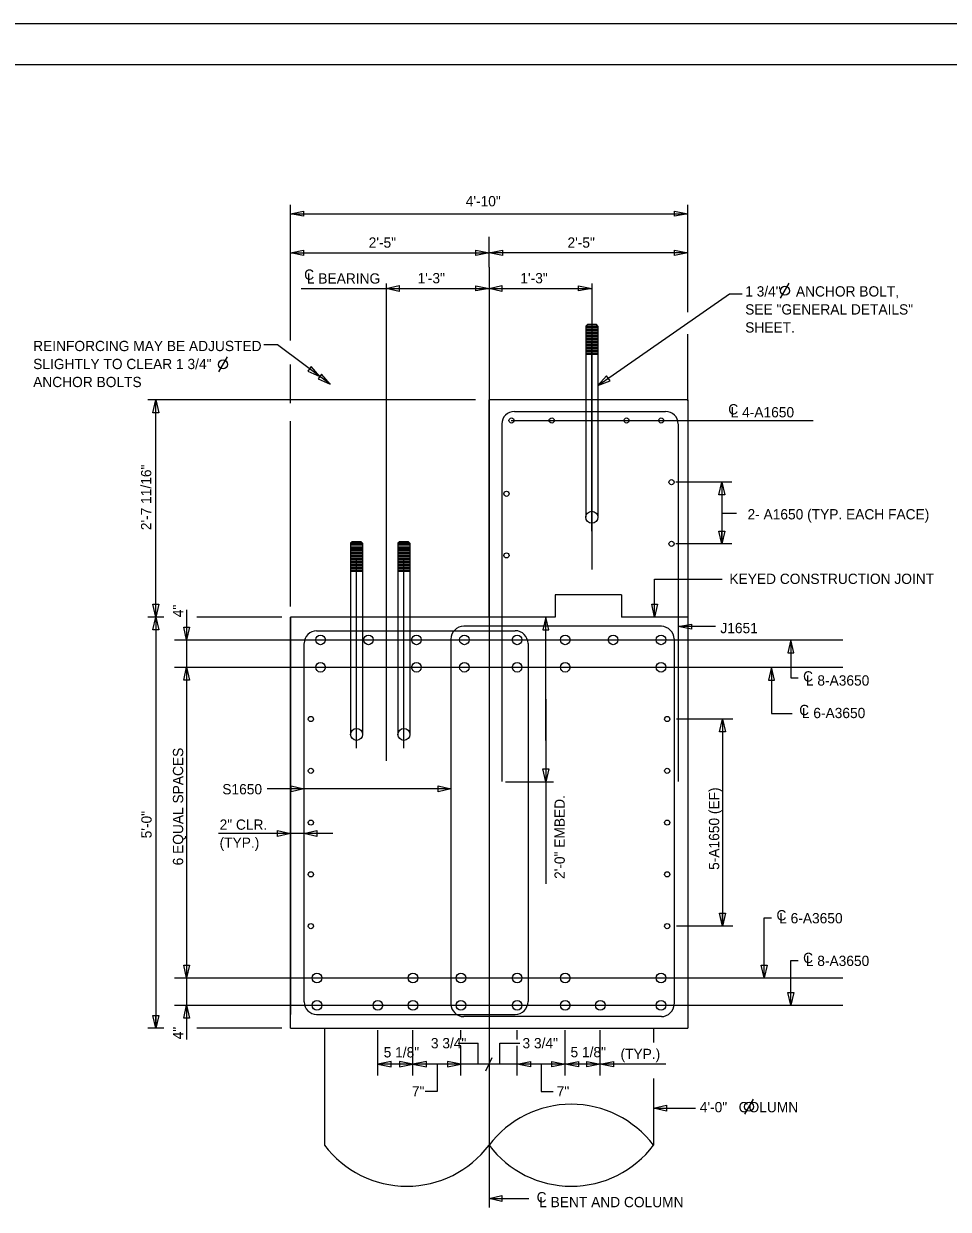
# Model space of a CAD drawing. Extents: x 1970675.2 to 1970711.3, y 796145.2 to 796167.2.
# Drawn here: x 1970689.32 to 1970700.57, y 796152.83 to 796167.25 of the extents above; entities that cross this region are included whole.
import ezdxf

# ---------------------------------------------------------------- set-up
doc = ezdxf.new("R2010")
doc.units = 0
for name, color, linetype in [('BR_AUTO DIMENSION', 7, 'Continuous'), ('BR_BORDER LINES', 7, 'Continuous'), ('BR_CENTER LINES', 7, 'Continuous'), ('BR_CONCRETE', 7, 'Continuous'), ('BR_REBAR', 7, 'Continuous'), ('BR_STRUCTURAL STEEL', 7, 'Continuous'), ('BR_TEXT', 7, 'Continuous'), ('Level 31', 7, 'Continuous')]:
    doc.layers.add(name, color=color, linetype=linetype)

msp = doc.modelspace()

# ---------------------------------------------------------------- linework, layer by layer
at = {"layer": 'BR_AUTO DIMENSION'}
for p, q in [((1970692.565, 796163.394), (1970692.565, 796165.043)), ((1970697.398, 796163.737), (1970697.398, 796165.043)), ((1970692.565, 796164.935), (1970697.398, 796164.935)), ((1970694.981, 796164.287), (1970694.981, 796164.655)), ((1970692.565, 796164.46), (1970694.981, 796164.46)), ((1970697.398, 796164.46), (1970694.981, 796164.46)), ((1970692.695, 796164.027), (1970693.731, 796164.027)), ((1970693.731, 796164.027), (1970694.981, 796164.027)), ((1970694.981, 796164.027), (1970696.231, 796164.027)), ((1970696.304, 796162.844), (1970697.905, 796163.961)), ((1970697.905, 796163.961), (1970698.058, 796163.961)), ((1970697.398, 796162.658), (1970697.398, 796163.469)), ((1970692.565, 796162.629), (1970692.565, 796163.1)), ((1970694.815, 796162.67), (1970690.832, 796162.67)), ((1970690.929, 796160.029), (1970690.929, 796162.67)), ((1970692.565, 796160.158), (1970692.565, 796162.414)), ((1970697.934, 796161.67), (1970697.252, 796161.67)), ((1970697.811, 796161.67), (1970697.811, 796160.92)), ((1970697.811, 796161.293), (1970697.989, 796161.293)), ((1970697.934, 796160.92), (1970697.252, 796160.92)), ((1970691.304, 796160.119), (1970691.304, 796154.893)), ((1970691.025, 796160.029), (1970690.832, 796160.029)), ((1970690.929, 796160.029), (1970690.929, 796155.029)), ((1970692.46, 796160.029), (1970691.427, 796160.029)), ((1970695.673, 796158.529), (1970695.673, 796160.029)), ((1970697.735, 796159.913), (1970697.282, 796159.913)), ((1970698.415, 796159.419), (1970698.415, 796158.857)), ((1970695.673, 796159.029), (1970695.673, 796156.786)), ((1970697.945, 796158.789), (1970697.262, 796158.789)), ((1970697.821, 796158.789), (1970697.821, 796156.27)), ((1970698.415, 796158.857), (1970698.666, 796158.857)), ((1970695.183, 796158.027), (1970695.766, 796158.027)), ((1970694.518, 796157.941), (1970692.285, 796157.941)), ((1970693.083, 796157.397), (1970691.69, 796157.397)), ((1970697.945, 796156.27), (1970697.262, 796156.27)), ((1970691.025, 796155.029), (1970690.832, 796155.029)), ((1970692.46, 796155.029), (1970691.427, 796155.029)), ((1970693.629, 796154.454), (1970693.629, 796155.006)), ((1970694.056, 796154.454), (1970694.056, 796155.006)), ((1970694.639, 796154.891), (1970694.639, 796155.006)), ((1970695.323, 796154.891), (1970695.323, 796155.006)), ((1970695.907, 796154.454), (1970695.907, 796155.006)), ((1970696.334, 796154.454), (1970696.334, 796155.006)), ((1970696.334, 796155.006), (1970696.334, 796155.006)), ((1970694.606, 796154.846), (1970694.849, 796154.846)), ((1970694.639, 796154.454), (1970694.639, 796154.815)), ((1970694.849, 796154.592), (1970694.849, 796154.846)), ((1970695.113, 796154.846), (1970695.356, 796154.846)), ((1970695.113, 796154.592), (1970695.113, 796154.846)), ((1970695.323, 796154.454), (1970695.323, 796154.815)), ((1970697.13, 796154.592), (1970693.629, 796154.592)), ((1970694.349, 796154.592), (1970694.349, 796154.259)), ((1970694.944, 796154.509), (1970695.019, 796154.674)), ((1970695.615, 796154.592), (1970695.615, 796154.259)), ((1970694.349, 796154.259), (1970694.205, 796154.259)), ((1970695.615, 796154.259), (1970695.759, 796154.259)), ((1970696.981, 796154.055), (1970697.493, 796154.055)), ((1970694.981, 796152.956), (1970695.464, 796152.956))]:
    msp.add_line(p, q, dxfattribs=at)
for points in [[(1970692.727, 796164.904), (1970692.565, 796164.935), (1970692.727, 796164.967)], [(1970697.235, 796164.967), (1970697.398, 796164.935), (1970697.235, 796164.904)], [(1970692.727, 796164.429), (1970692.565, 796164.46), (1970692.727, 796164.491)], [(1970694.819, 796164.491), (1970694.981, 796164.46), (1970694.819, 796164.429)], [(1970695.144, 796164.429), (1970694.981, 796164.46), (1970695.144, 796164.491)], [(1970697.235, 796164.491), (1970697.398, 796164.46), (1970697.235, 796164.429)], [(1970693.887, 796163.991), (1970693.731, 796164.027), (1970693.887, 796164.063)], [(1970694.819, 796164.058), (1970694.981, 796164.027), (1970694.819, 796163.996)], [(1970695.137, 796163.991), (1970694.981, 796164.027), (1970695.137, 796164.063)], [(1970696.069, 796164.058), (1970696.231, 796164.027), (1970696.069, 796163.996)], [(1970692.777, 796163.021), (1970692.924, 796162.956), (1970692.82, 796163.078)], [(1970692.902, 796162.927), (1970693.049, 796162.863), (1970692.945, 796162.985)], [(1970696.411, 796162.963), (1970696.304, 796162.844), (1970696.453, 796162.904)], [(1970690.893, 796162.514), (1970690.929, 796162.67), (1970690.965, 796162.514)], [(1970697.775, 796161.514), (1970697.811, 796161.67), (1970697.847, 796161.514)], [(1970697.847, 796161.076), (1970697.811, 796160.92), (1970697.775, 796161.076)], [(1970690.965, 796160.185), (1970690.929, 796160.029), (1970690.893, 796160.185)], [(1970697.031, 796160.185), (1970696.995, 796160.029), (1970696.959, 796160.185)], [(1970690.893, 796159.873), (1970690.929, 796160.029), (1970690.965, 796159.873)], [(1970691.34, 796159.908), (1970691.304, 796159.752), (1970691.268, 796159.908)], [(1970695.709, 796159.873), (1970695.673, 796160.029), (1970695.637, 796159.873)], [(1970697.445, 796159.882), (1970697.282, 796159.913), (1970697.445, 796159.944)], [(1970698.687, 796159.596), (1970698.651, 796159.752), (1970698.615, 796159.596)], [(1970691.268, 796159.263), (1970691.304, 796159.419), (1970691.34, 796159.263)], [(1970698.451, 796159.263), (1970698.415, 796159.419), (1970698.379, 796159.263)], [(1970697.785, 796158.633), (1970697.821, 796158.789), (1970697.857, 796158.633)], [(1970695.709, 796158.183), (1970695.673, 796158.027), (1970695.637, 796158.183)], [(1970692.575, 796157.977), (1970692.731, 796157.941), (1970692.575, 796157.905)], [(1970694.362, 796157.977), (1970694.518, 796157.941), (1970694.362, 796157.905)], [(1970692.409, 796157.433), (1970692.565, 796157.397), (1970692.409, 796157.361)], [(1970692.887, 796157.361), (1970692.731, 796157.397), (1970692.887, 796157.433)], [(1970697.857, 796156.426), (1970697.821, 796156.27), (1970697.785, 796156.426)], [(1970691.34, 796155.796), (1970691.304, 796155.64), (1970691.268, 796155.796)], [(1970698.363, 796155.796), (1970698.327, 796155.64), (1970698.291, 796155.796)], [(1970698.687, 796155.463), (1970698.651, 796155.307), (1970698.615, 796155.463)], [(1970691.268, 796155.151), (1970691.304, 796155.307), (1970691.34, 796155.151)], [(1970690.965, 796155.185), (1970690.929, 796155.029), (1970690.893, 796155.185)], [(1970693.791, 796154.623), (1970693.629, 796154.592), (1970693.791, 796154.56)], [(1970693.894, 796154.56), (1970694.056, 796154.592), (1970693.894, 796154.623)], [(1970694.219, 796154.623), (1970694.056, 796154.592), (1970694.219, 796154.56)], [(1970694.477, 796154.56), (1970694.639, 796154.592), (1970694.477, 796154.623)], [(1970695.486, 796154.56), (1970695.323, 796154.592), (1970695.486, 796154.623)], [(1970695.744, 796154.623), (1970695.907, 796154.592), (1970695.744, 796154.56)], [(1970696.069, 796154.56), (1970695.907, 796154.592), (1970696.069, 796154.623)], [(1970696.171, 796154.623), (1970696.334, 796154.592), (1970696.171, 796154.56)], [(1970696.496, 796154.56), (1970696.334, 796154.592), (1970696.496, 796154.623)], [(1970697.137, 796154.019), (1970696.981, 796154.055), (1970697.137, 796154.091)], [(1970695.137, 796152.92), (1970694.981, 796152.956), (1970695.137, 796152.992)]]:
    msp.add_lwpolyline(points, close=True, dxfattribs=at)
for points in [[(1970693.049, 796162.863), (1970692.408, 796163.342), (1970692.243, 796163.342)], [(1970696.995, 796160.029), (1970696.995, 796160.492), (1970697.816, 796160.492)], [(1970698.651, 796159.752), (1970698.651, 796159.289), (1970698.739, 796159.289)], [(1970698.327, 796155.64), (1970698.327, 796156.372), (1970698.415, 796156.372)], [(1970698.651, 796155.307), (1970698.651, 796155.853), (1970698.739, 796155.853)]]:
    msp.add_lwpolyline(points, dxfattribs=at)
at = {"layer": 'BR_BORDER LINES'}
msp.add_line((1970710.736, 796166.746), (1970677.07, 796166.746), dxfattribs=at)
at = {"layer": 'BR_CENTER LINES'}
for p, q in [((1970694.981, 796164.287), (1970694.981, 796152.849)), ((1970693.731, 796164.087), (1970693.731, 796158.28)), ((1970696.231, 796164.087), (1970696.231, 796160.609)), ((1970696.231, 796161.076), (1970696.231, 796163.376)), ((1970695.251, 796162.42), (1970698.921, 796162.42)), ((1970693.371, 796158.436), (1970693.371, 796160.735)), ((1970693.946, 796158.436), (1970693.946, 796160.735)), ((1970691.157, 796159.752), (1970699.284, 796159.752)), ((1970691.157, 796159.419), (1970699.284, 796159.419)), ((1970691.157, 796155.64), (1970699.284, 796155.64)), ((1970691.157, 796155.307), (1970699.284, 796155.307))]:
    msp.add_line(p, q, dxfattribs=at)
at = {"layer": 'BR_CONCRETE'}
for p, q in [((1970694.981, 796160.029), (1970694.981, 796162.67)), ((1970697.398, 796162.67), (1970694.981, 796162.67)), ((1970697.398, 796162.67), (1970697.398, 796160.029)), ((1970696.592, 796160.298), (1970695.787, 796160.298)), ((1970695.787, 796160.298), (1970695.787, 796160.029)), ((1970696.592, 796160.298), (1970696.592, 796160.029)), ((1970692.565, 796160.029), (1970692.565, 796155.196)), ((1970692.565, 796155.029), (1970692.565, 796160.029)), ((1970694.981, 796160.029), (1970692.565, 796160.029)), ((1970695.787, 796160.029), (1970694.981, 796160.029)), ((1970697.398, 796160.029), (1970696.592, 796160.029)), ((1970697.398, 796160.029), (1970697.398, 796155.029)), ((1970692.565, 796155.029), (1970697.398, 796155.029)), ((1970692.981, 796155.029), (1970692.981, 796153.605)), ((1970696.981, 796155.029), (1970696.981, 796154.856)), ((1970696.981, 796154.418), (1970696.981, 796153.605))]:
    msp.add_line(p, q, dxfattribs=at)
for centre, start, end in [((1970695.981, 796152.851), 37.0023, 142.9977), ((1970693.981, 796154.359), 217.0023, 322.9977), ((1970695.981, 796154.359), 217.0023, 322.9977)]:
    msp.add_arc(centre, 1.252, start, end, dxfattribs=at)
at = {"layer": 'BR_REBAR'}
for p, q in [((1970695.29, 796162.531), (1970697.128, 796162.531)), ((1970695.136, 796162.377), (1970695.136, 796158.029)), ((1970697.282, 796162.377), (1970697.282, 796158.029)), ((1970697.077, 796159.917), (1970694.674, 796159.917)), ((1970692.885, 796159.863), (1970695.299, 796159.863)), ((1970694.518, 796159.761), (1970694.518, 796155.325)), ((1970697.231, 796159.764), (1970697.231, 796155.323)), ((1970692.731, 796159.709), (1970692.731, 796155.35)), ((1970695.455, 796159.707), (1970695.455, 796155.352)), ((1970692.885, 796155.196), (1970695.299, 796155.196)), ((1970697.078, 796155.169), (1970694.674, 796155.169))]:
    msp.add_line(p, q, dxfattribs=at)
for centre, radius in [((1970695.255, 796162.42), 0.0313), ((1970695.743, 796162.42), 0.0313), ((1970696.653, 796162.42), 0.0313), ((1970697.075, 796162.42), 0.0313), ((1970697.2, 796161.67), 0.0313), ((1970695.193, 796161.529), 0.0313), ((1970697.2, 796160.92), 0.0313), ((1970695.193, 796160.779), 0.0313), ((1970692.932, 796159.752), 0.0588), ((1970693.515, 796159.752), 0.0588), ((1970694.099, 796159.752), 0.0588), ((1970694.682, 796159.752), 0.0588), ((1970695.323, 796159.752), 0.0588), ((1970695.907, 796159.752), 0.0588), ((1970696.49, 796159.752), 0.0588), ((1970697.073, 796159.752), 0.0588), ((1970692.932, 796159.419), 0.0588), ((1970694.099, 796159.419), 0.0588), ((1970694.682, 796159.419), 0.0588), ((1970695.323, 796159.419), 0.0588), ((1970695.907, 796159.419), 0.0588), ((1970697.073, 796159.419), 0.0588), ((1970692.815, 796158.789), 0.0313), ((1970697.148, 796158.789), 0.0313), ((1970692.815, 796158.159), 0.0313), ((1970697.148, 796158.159), 0.0313), ((1970692.815, 796157.529), 0.0313), ((1970697.148, 796157.529), 0.0313), ((1970692.815, 796156.9), 0.0313), ((1970697.148, 796156.9), 0.0313), ((1970692.815, 796156.27), 0.0313), ((1970697.148, 796156.27), 0.0313), ((1970692.889, 796155.64), 0.0588), ((1970694.056, 796155.64), 0.0588), ((1970694.639, 796155.64), 0.0588), ((1970695.323, 796155.64), 0.0588), ((1970695.907, 796155.64), 0.0588), ((1970697.073, 796155.64), 0.0588), ((1970692.889, 796155.307), 0.0588), ((1970693.629, 796155.307), 0.0588), ((1970694.056, 796155.307), 0.0588), ((1970694.639, 796155.307), 0.0588), ((1970695.323, 796155.307), 0.0588), ((1970695.907, 796155.307), 0.0588), ((1970696.334, 796155.307), 0.0588), ((1970697.073, 796155.307), 0.0588)]:
    msp.add_circle(centre, radius, dxfattribs=at)
for centre, start, end in [((1970695.292, 796162.375), 91.025, 178.975), ((1970697.126, 796162.375), 1.025, 88.975), ((1970694.674, 796159.761), 90, 180), ((1970697.075, 796159.761), 1.025, 88.975), ((1970692.888, 796159.707), 91.025, 178.975), ((1970695.299, 796159.707), 0, 90), ((1970692.888, 796155.352), 181.025, 268.975), ((1970694.674, 796155.325), 180, 270), ((1970695.299, 796155.352), 270, 0), ((1970697.075, 796155.325), 271.025, 358.975)]:
    msp.add_arc(centre, 0.156, start, end, dxfattribs=at)
at = {"layer": 'BR_STRUCTURAL STEEL'}
for p, q in [((1970696.177, 796163.587), (1970696.158, 796163.569)), ((1970696.304, 796163.569), (1970696.158, 796163.569)), ((1970696.158, 796163.569), (1970696.158, 796162.67)), ((1970696.304, 796163.551), (1970696.158, 796163.551)), ((1970696.304, 796163.532), (1970696.158, 796163.532)), ((1970696.304, 796163.514), (1970696.158, 796163.514)), ((1970696.286, 796163.587), (1970696.177, 796163.587)), ((1970696.304, 796163.569), (1970696.286, 796163.587)), ((1970696.304, 796163.569), (1970696.304, 796162.67)), ((1970696.304, 796163.496), (1970696.158, 796163.496)), ((1970696.304, 796163.478), (1970696.158, 796163.478)), ((1970696.304, 796163.459), (1970696.158, 796163.459)), ((1970696.304, 796163.441), (1970696.158, 796163.441)), ((1970696.304, 796163.423), (1970696.158, 796163.423)), ((1970696.304, 796163.405), (1970696.158, 796163.405)), ((1970696.304, 796163.386), (1970696.158, 796163.386)), ((1970696.304, 796163.368), (1970696.158, 796163.368)), ((1970696.304, 796163.35), (1970696.158, 796163.35)), ((1970696.304, 796163.332), (1970696.158, 796163.332)), ((1970696.304, 796163.314), (1970696.158, 796163.314)), ((1970696.304, 796163.295), (1970696.158, 796163.295)), ((1970696.304, 796163.277), (1970696.158, 796163.277)), ((1970696.304, 796163.259), (1970696.158, 796163.259)), ((1970696.304, 796163.241), (1970696.158, 796163.241)), ((1970696.304, 796163.222), (1970696.158, 796163.222)), ((1970696.158, 796162.67), (1970696.158, 796161.243)), ((1970696.304, 796162.67), (1970696.304, 796161.246)), ((1970693.316, 796160.946), (1970693.298, 796160.928)), ((1970693.444, 796160.928), (1970693.298, 796160.928)), ((1970693.298, 796160.928), (1970693.298, 796160.029)), ((1970693.444, 796160.91), (1970693.298, 796160.91)), ((1970693.426, 796160.946), (1970693.316, 796160.946)), ((1970693.444, 796160.928), (1970693.426, 796160.946)), ((1970693.444, 796160.928), (1970693.444, 796160.029)), ((1970693.891, 796160.946), (1970693.873, 796160.928)), ((1970694.019, 796160.928), (1970693.873, 796160.928)), ((1970693.873, 796160.928), (1970693.873, 796160.029)), ((1970694.019, 796160.91), (1970693.873, 796160.91)), ((1970694.001, 796160.946), (1970693.891, 796160.946)), ((1970694.019, 796160.928), (1970694.001, 796160.946)), ((1970694.019, 796160.928), (1970694.019, 796160.029)), ((1970693.444, 796160.892), (1970693.298, 796160.892)), ((1970693.444, 796160.873), (1970693.298, 796160.873)), ((1970693.444, 796160.855), (1970693.298, 796160.855)), ((1970693.444, 796160.837), (1970693.298, 796160.837)), ((1970693.444, 796160.819), (1970693.298, 796160.819)), ((1970693.444, 796160.801), (1970693.298, 796160.801)), ((1970693.444, 796160.782), (1970693.298, 796160.782)), ((1970693.444, 796160.764), (1970693.298, 796160.764)), ((1970694.019, 796160.892), (1970693.873, 796160.892)), ((1970694.019, 796160.873), (1970693.873, 796160.873)), ((1970694.019, 796160.855), (1970693.873, 796160.855)), ((1970694.019, 796160.837), (1970693.873, 796160.837)), ((1970694.019, 796160.819), (1970693.873, 796160.819)), ((1970694.019, 796160.801), (1970693.873, 796160.801)), ((1970694.019, 796160.782), (1970693.873, 796160.782)), ((1970694.019, 796160.764), (1970693.873, 796160.764)), ((1970693.444, 796160.746), (1970693.298, 796160.746)), ((1970693.444, 796160.728), (1970693.298, 796160.728)), ((1970693.444, 796160.709), (1970693.298, 796160.709)), ((1970693.444, 796160.691), (1970693.298, 796160.691)), ((1970693.444, 796160.673), (1970693.298, 796160.673)), ((1970693.444, 796160.655), (1970693.298, 796160.655)), ((1970693.444, 796160.636), (1970693.298, 796160.636)), ((1970694.019, 796160.746), (1970693.873, 796160.746)), ((1970694.019, 796160.728), (1970693.873, 796160.728)), ((1970694.019, 796160.709), (1970693.873, 796160.709)), ((1970694.019, 796160.691), (1970693.873, 796160.691)), ((1970694.019, 796160.673), (1970693.873, 796160.673)), ((1970694.019, 796160.655), (1970693.873, 796160.655)), ((1970694.019, 796160.636), (1970693.873, 796160.636)), ((1970693.444, 796160.618), (1970693.298, 796160.618)), ((1970693.444, 796160.6), (1970693.298, 796160.6)), ((1970693.444, 796160.582), (1970693.298, 796160.582)), ((1970694.019, 796160.618), (1970693.873, 796160.618)), ((1970694.019, 796160.6), (1970693.873, 796160.6)), ((1970694.019, 796160.582), (1970693.873, 796160.582)), ((1970693.298, 796160.029), (1970693.298, 796158.602)), ((1970693.444, 796160.029), (1970693.444, 796158.605)), ((1970693.873, 796160.029), (1970693.873, 796158.602)), ((1970694.019, 796160.029), (1970694.019, 796158.605))]:
    msp.add_line(p, q, dxfattribs=at)
for centre in [(1970696.231, 796161.243), (1970693.371, 796158.602), (1970693.946, 796158.602)]:
    msp.add_circle(centre, 0.0729, dxfattribs=at)
at = {"layer": 'BR_TEXT'}
for p, q in [((1970698.527, 796163.907), (1970698.632, 796164.089)), ((1970691.694, 796163.011), (1970691.799, 796163.193)), ((1970697.811, 796160.92), (1970697.811, 796161.068)), ((1970697.821, 796156.27), (1970697.821, 796156.418)), ((1970690.929, 796155.029), (1970690.929, 796155.177)), ((1970698.091, 796153.982), (1970698.196, 796154.164))]:
    msp.add_line(p, q, dxfattribs=at)
for centre in [(1970698.579, 796163.998), (1970691.747, 796163.102), (1970698.143, 796154.073)]:
    msp.add_circle(centre, 0.055, dxfattribs=at)
at = {"layer": 'Level 31'}
msp.add_lwpolyline([(1970675.236, 796145.246), (1970711.236, 796145.246), (1970711.236, 796167.246), (1970675.236, 796167.246)], close=True, dxfattribs=at)

# ---------------------------------------------------------------- texts
at = {"layer": 'BR_AUTO DIMENSION'}
for s, p in [('4\'-10"', (1970694.698, 796165.025)), ('2\'-5"', (1970693.518, 796164.522)), ('2\'-5"', (1970695.935, 796164.522))]:
    msp.add_text(s, height=0.125, dxfattribs=at).set_placement(p)
at = {"layer": 'BR_TEXT'}
for s, p in [('C', (1970692.733, 796164.132)), ('L BEARING', (1970692.766, 796164.085)), ('1\'-3"', (1970694.112, 796164.089)), ('1\'-3"', (1970695.362, 796164.089)), ('C', (1970697.89, 796162.494)), ('L 4-A1650', (1970697.919, 796162.458)), ('2- A1650 (TYP. EACH FACE)', (1970698.124, 796161.217)), ('KEYED CONSTRUCTION JOINT', (1970697.904, 796160.432)), ('J1651', (1970697.794, 796159.833)), ('S1650', (1970691.738, 796157.873)), ('2" CLR.', (1970691.705, 796157.442)), ('(TYP.)', (1970691.705, 796157.223)), ('3 3/4"', (1970694.274, 796154.784)), ('3 3/4"', (1970695.388, 796154.784))]:
    msp.add_text(s, height=0.125, dxfattribs=at).set_placement(p)
for s, rotation, p in [('1 3/4"    ANCHOR BOLT, ', 360, (1970698.096, 796163.928)), ('SEE "GENERAL DETAILS"', 360, (1970698.096, 796163.709)), ('SHEET.', 360, (1970698.096, 796163.49)), ('REINFORCING MAY BE ADJUSTED', 360, (1970689.438, 796163.264)), ('SLIGHTLY TO CLEAR 1 3/4"  ', 360, (1970689.438, 796163.045)), ('ANCHOR BOLTS', 360, (1970689.438, 796162.826)), ('2\'-7 11/16"', 90, (1970690.874, 796161.086)), ('4"', 90, (1970691.262, 796160.027)), ('C', 360, (1970698.8, 796159.245)), ('L 8-A3650', 360, (1970698.834, 796159.196)), ('C', 360, (1970698.753, 796158.836)), ('L 6-A3650', 360, (1970698.785, 796158.8)), ('6 EQUAL SPACES', 90, (1970691.262, 796157.009)), ('5-A1650 (EF)', 90, (1970697.78, 796156.954)), ('2\'-0" EMBED.', 90, (1970695.902, 796156.844)), ('5\'-0"', 90, (1970690.878, 796157.338)), ('C', 360, (1970698.476, 796156.34)), ('L 6-A3650', 360, (1970698.509, 796156.304)), ('C', 360, (1970698.8, 796155.821)), ('L 8-A3650', 360, (1970698.833, 796155.785)), ('4"', 90, (1970691.262, 796154.893)), ('5 1/8"', 360, (1970693.7, 796154.673)), ('5 1/8"', 360, (1970695.972, 796154.675)), ('(TYP.)', 360, (1970696.58, 796154.653)), ('7"', 360, (1970694.043, 796154.198)), ('7"', 360, (1970695.804, 796154.198)), ('4\'-0"   COLUMN', 360, (1970697.544, 796154.006)), ('C', 360, (1970695.56, 796152.91)), ('L BENT AND COLUMN', 360, (1970695.591, 796152.851))]:
    msp.add_text(s, height=0.125, rotation=rotation, dxfattribs=at).set_placement(p)

doc.saveas('drawing.dxf')
